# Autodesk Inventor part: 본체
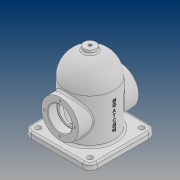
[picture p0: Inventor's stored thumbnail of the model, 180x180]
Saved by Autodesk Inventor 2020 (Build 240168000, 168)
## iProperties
Created: 2021-08
Part Number: 본체
Material: 일반
Document SubType Name: Modeling
Designer: PC312-
Density: 1 g/cm^3
Appearance: 기본값
Author: PC312-
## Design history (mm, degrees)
sketch "스케치1"
  geometry: C1 r 40 at (0, 0); 1 further point
  constraints: 1 centre point, 1 coincident
  dimensions: "d0" = 80 diameter of C1
extrude "돌출1" new body sketch "스케치1" distance "d1" = 48; taper "d2" = 0 deg
sketch "스케치2"
  geometry: C1 r 40 at (0, 0) reference; 1 further point
extrude "돌출2" join sketch "스케치2" distance "d3" = 36; taper "d4" = 0 deg
sketch "스케치3"
  geometry: L1 (-40, -48)-(40, -48) reference; L2 (0, -4)-(0, 76); A1 r 40 centre (0, 36) between (0, -4) and (0, 76); 1 further point
  constraints: 2 end point, 2 point on circle, 1 centre point, 1 midpoint, 1 vertical, 1 vertical alignment
  dimensions: "d5" = 80 diameter of A1; "d7" = 84 distance from line of L1 A1.centre
revolve "회전1" sketch "스케치3" stored, may be unused: angle "d8" = 280 deg
feature "쉘1" dims "d10" = 8
sketch "스케치4"
  geometry: L1 (55, 55)-(-55, 55); L2 (-55, 55)-(-55, -55); L3 (-55, -55)-(55, -55); L4 (55, -55)-(55, 55); L5 (55, 55)-(-55, -55); L6 (-55, 55)-(55, -55); C1 r 32 at (0, 0) reference; 1 further point
  constraints: 12 end point, 2 midpoint, 2 parallel, 1 horizontal, 1 perpendicular
  dimensions: "d11" = 110 distance of L3.end L2.end; "d12" = 110 distance of L2.end L1.end
extrude "돌출3" join sketch "스케치4" distance "d13" = 10; taper "d14" = 0 deg
node "작업 평면2"
sketch "스케치5"
  geometry: C1 r 31 at (0, 0); 1 further point
  constraints: 1 centre point, 1 coincident
  dimensions: "d16" = 62 diameter of C1
extrude "돌출4" join sketch "스케치5" stored distance "d17" = 10; taper "d18" = 0 deg
sketch "스케치6" dims "d19" = 51
  geometry: 3 further points
  constraints: 2 vertical alignment, 1 coincident, 2 other
hole "구멍1" sketch "스케치6" at (0, 25.5) diameter "d20" = 3.242; stored, may be unused: countersink angle "d24" = 90 deg, drill point angle "d26" = 118 deg; dims "d21" = 8, "d22" = 4, "d23" = 2, "d25" = 10
sketch "스케치7"
  geometry: C1 r 31 at (0, 0) reference; 2 further points
  constraints: 1 coincident
hole "구멍2" sketch "스케치7" at (0, 0) diameter "d30" = 33; stored, may be unused: countersink angle "d34" = 90 deg, drill point angle "d36" = 0 deg; dims "d31" = 8, "d32" = 40, "d33" = 15, "d35" = 10
node "작업 평면3"
sketch "스케치8"
  geometry: C1 r 10 at (0, 0); 1 further point
  constraints: 1 centre point, 1 coincident
  dimensions: "d38" = 20 diameter of C1
extrude "돌출5" join sketch "스케치8" stored distance "d39" = 10; taper "d40" = 0 deg
sketch "스케치9"
  geometry: C1 r 10 at (0, 0) reference; 2 further points
  constraints: 1 coincident
hole "구멍3" sketch "스케치9" at (0, 0) diameter "d41" = 5.1881; stored, may be unused: countersink angle "d45" = 90 deg, drill point angle "d47" = 0 deg; dims "d42" = 12, "d43" = 40, "d44" = 15, "d46" = 16
fillet "모깎기1" dims "d48" = 12
sketch "스케치10"
  geometry: A1 r 12 centre (-43, -43) between (-55, -43) and (-43, -55) reference; A2 r 12 centre (-43, 43) between (-43, 55) and (-55, 43) reference; A3 r 12 centre (43, 43) between (55, 43) and (43, 55) reference; A4 r 12 centre (43, -43) between (43, -55) and (55, -43) reference; 5 further points
  constraints: 4 coincident
hole "구멍4" sketch "스케치10" at (-43, -43), (-43, 43), (43, 43), (43, -43) diameter "d49" = 9; stored, may be unused: countersink angle "d53" = 90 deg, drill point angle "d55" = 0 deg; dims "d50" = 12, "d51" = 40, "d52" = 15, "d54" = 16
node "작업 평면4"
sketch "스케치11"
  geometry: L1 (-48, -43)-(-48, 43) reference; 2 further points
  constraints: 1 other
  dimensions: "d57" = 48 distance from line of L1 point (0, -0.099)
feature "엠보싱1" sketch "스케치11" dims "d1" = 48, "d2" = 0, "d10" = 8, "d58" = 0.5, "d59" = 0
fillet "모깎기2" dims "d60" = 0.3
fillet "모깎기3" dims "d61" = 3
chamfer "모따기1" distance "d62" = 1; stored, may be unused: second distance "d63" = 2, angle "d64" = 45 deg
node "솔리드1"
pattern_circular "원형 패턴1" dims angle "d28" = 360 deg
mirror "미러1"
feature "A9D066F2-1C7D-4E18-AEED-F7BC21143FA4" dims "d49" = 9, "d50" = 12, "d51" = 40, "d52" = 15, "d53" = 90 deg, "d54" = 16, "d55" = 0
other parameters: "d37" = -129, "d56" = 64.75
